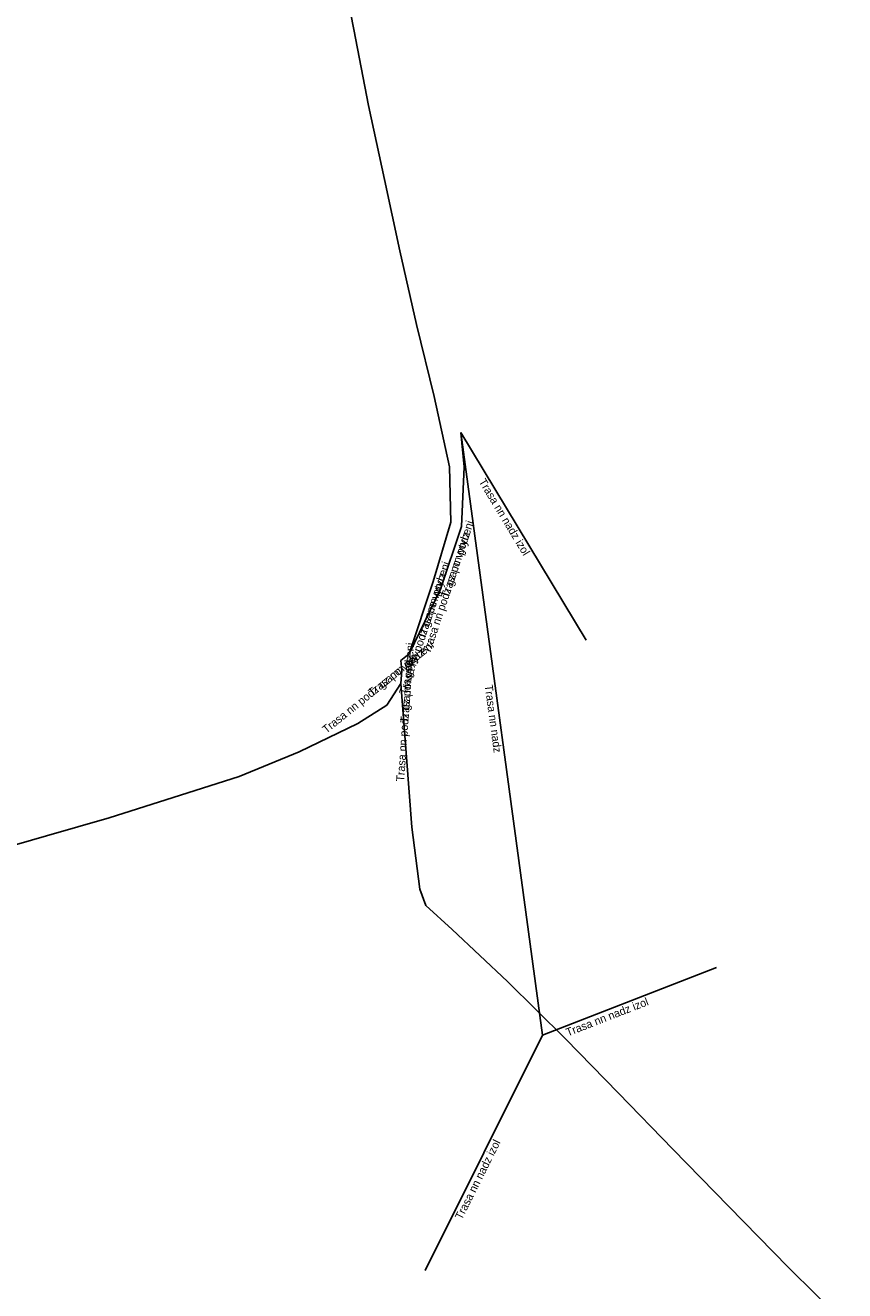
# Model space of a CAD drawing. Extents: x -817778 to -817398, y -1067927 to -1067625.
# Drawn here: x -817493 to -817441.8, y -1067829.5 to -1067750.4 of the extents above; entities that cross this region are included whole.
import ezdxf

# ---------------------------------------------------------------- set-up
doc = ezdxf.new("R2010")
doc.units = 0
doc.layers.add('Popiskový text - Ostatní atributy Trasy', color=7, linetype='Continuous')
doc.layers.add('Spojnice NN', color=7, linetype='Continuous')

msp = doc.modelspace()

# ---------------------------------------------------------------- linework, layer by layer
at = {"layer": 'Spojnice NN'}
for points in [[(-817466.4, -1067781.49), (-817466.48, -1067778.03), (-817467.44, -1067773.64), (-817468.53, -1067769.14), (-817469.58, -1067764.54), (-817470.53, -1067760.07), (-817471.53, -1067755.45), (-817472.46, -1067750.71), (-817473.33, -1067746.22), (-817473.29, -1067744.79), (-817472.61, -1067742.31), (-817471.77, -1067738.94), (-817471.89, -1067734.16), (-817472.39, -1067728.74), (-817472.7, -1067724.1), (-817472.86, -1067719.09), (-817473.02, -1067714.46), (-817473.04, -1067709.3), (-817472.5, -1067704.79), (-817471.63, -1067700.15), (-817471.4, -1067695.35), (-817471.84, -1067690.23), (-817471.91, -1067684.93), (-817471.5, -1067679.34)], [(-817466.4, -1067781.49), (-817466.48, -1067778.03), (-817467.44, -1067773.64), (-817468.53, -1067769.14), (-817469.58, -1067764.54), (-817470.53, -1067760.07), (-817471.53, -1067755.45), (-817472.46, -1067750.71), (-817473.33, -1067746.22), (-817473.29, -1067744.79), (-817472.61, -1067742.31), (-817471.77, -1067738.94), (-817471.89, -1067734.16), (-817472.39, -1067728.74), (-817472.7, -1067724.1), (-817472.86, -1067719.09), (-817473.02, -1067714.46), (-817473.04, -1067709.3), (-817472.5, -1067704.79), (-817471.63, -1067700.15), (-817471.4, -1067695.35), (-817471.84, -1067690.23), (-817471.91, -1067684.93), (-817471.5, -1067679.34)], [(-817469, -1067789.72), (-817467.03, -1067785.68), (-817465.72, -1067781.75), (-817465.55, -1067778.03), (-817465.76, -1067775.89)], [(-817469, -1067789.72), (-817467.03, -1067785.68), (-817465.72, -1067781.75), (-817465.55, -1067778.03), (-817465.76, -1067775.89)], [(-817465.76, -1067775.89), (-817460.665, -1067813.548)], [(-817465.76, -1067775.89), (-817457.936, -1067788.859)], [(-817469, -1067789.72), (-817467.5, -1067785.19), (-817466.4, -1067781.49)], [(-817469, -1067789.72), (-817467.5, -1067785.19), (-817466.4, -1067781.49)], [(-817469.52, -1067791.58), (-817469.46, -1067790.76), (-817469.51, -1067790.13)], [(-817469.52, -1067791.58), (-817469.46, -1067790.76), (-817469.51, -1067790.13)], [(-817469.51, -1067790.13), (-817469, -1067789.72)], [(-817469.51, -1067790.13), (-817469, -1067789.72)], [(-817546.215, -1067810.04), (-817543.44, -1067809.91), (-817538.61, -1067809.68), (-817533.97, -1067809.22), (-817529.37, -1067808.83), (-817524.86, -1067808.13), (-817520.32, -1067807.35), (-817516.2, -1067806.6), (-817511.99, -1067805.84), (-817507.85, -1067805.09), (-817503.69, -1067804.2), (-817499.55, -1067803.24), (-817495.57, -1067802.22), (-817491.66, -1067801.09), (-817487.75, -1067799.96), (-817483.74, -1067798.69), (-817479.63, -1067797.39), (-817475.88, -1067795.84), (-817472.2, -1067794.06), (-817470.4, -1067792.92), (-817469.52, -1067791.58)], [(-817546.215, -1067810.04), (-817543.44, -1067809.91), (-817538.61, -1067809.68), (-817533.97, -1067809.22), (-817529.37, -1067808.83), (-817524.86, -1067808.13), (-817520.32, -1067807.35), (-817516.2, -1067806.6), (-817511.99, -1067805.84), (-817507.85, -1067805.09), (-817503.69, -1067804.2), (-817499.55, -1067803.24), (-817495.57, -1067802.22), (-817491.66, -1067801.09), (-817487.75, -1067799.96), (-817483.74, -1067798.69), (-817479.63, -1067797.39), (-817475.88, -1067795.84), (-817472.2, -1067794.06), (-817470.4, -1067792.92), (-817469.52, -1067791.58)], [(-817441.78, -1067831.54), (-817445.32, -1067828.05), (-817449.03, -1067824.25), (-817452.51, -1067820.67), (-817455.91, -1067817.18), (-817459.22, -1067813.77), (-817462.86, -1067810.19), (-817466.32, -1067806.95), (-817467.95, -1067805.44), (-817468.34, -1067804.43), (-817468.82, -1067800.54), (-817469.16, -1067796.17), (-817469.52, -1067791.58)], [(-817441.78, -1067831.54), (-817445.32, -1067828.05), (-817449.03, -1067824.25), (-817452.51, -1067820.67), (-817455.91, -1067817.18), (-817459.22, -1067813.77), (-817462.86, -1067810.19), (-817466.32, -1067806.95), (-817467.95, -1067805.44), (-817468.34, -1067804.43), (-817468.82, -1067800.54), (-817469.16, -1067796.17), (-817469.52, -1067791.58)], [(-817460.665, -1067813.548), (-817449.792, -1067809.314)], [(-817460.665, -1067813.548), (-817468, -1067828.255)]]:
    msp.add_lwpolyline(points, dxfattribs=at)

# ---------------------------------------------------------------- texts
at = {"layer": 'Popiskový text - Ostatní atributy Trasy'}
for s, rotation, p in [('Trasa nn nadz izol', 301.10324, (-817464.672, -1067778.951)), ('Trasa nn podz gz po vytyceni', 71.56505, (-817467.701, -1067789.748)), ('Trasa nn podz', 71.56505, (-817466.535, -1067786.252)), ('Trasa nn podz gz po vytyceni', 71.67896, (-817469.174, -1067792.314)), ('Trasa nn podz', 71.67896, (-817468.016, -1067788.816)), ('Trasa nn podz gz po vytyceni', 38.79655, (-817474.173, -1067794.713)), ('Trasa nn podz', 38.79655, (-817471.301, -1067792.404)), ('Trasa nn podz gz po vytyceni', 85.81508, (-817469.317, -1067797.717)), ('Trasa nn podz', 85.81508, (-817469.048, -1067794.041)), ('Trasa nn nadz', 277.70497, (-817464.279, -1067791.687)), ('Trasa nn nadz izol', 21.27893, (-817459.083, -1067813.63)), ('Trasa nn nadz izol', 63.49293, (-817465.709, -1067825.12))]:
    msp.add_text(s, height=0.5, rotation=rotation, dxfattribs=at).set_placement(p)

doc.saveas('drawing.dxf')
